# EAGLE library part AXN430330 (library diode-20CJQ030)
Matsushita P8 NARROW-PITCH CONNECTORS FOR PC BOARDS 30Pin Header NARROW-PITCH (0.8mm) CONNECTORS P8 SERIES FEATURES The product lineup consists of the low profile of: - 3 mm - 3.5 mm - 4 mm - 4.5 mm - 5 mm - 5.5 mm - 6 mm - 7 mm - 8 mm - 11.5 mm - 13 mm - 14 mm APPLICATIONS Small portable equipment, laptop computers, video equipment, radio communication, cellular telephones, etc. Please send any comments to: messi@users.sourceforge.net
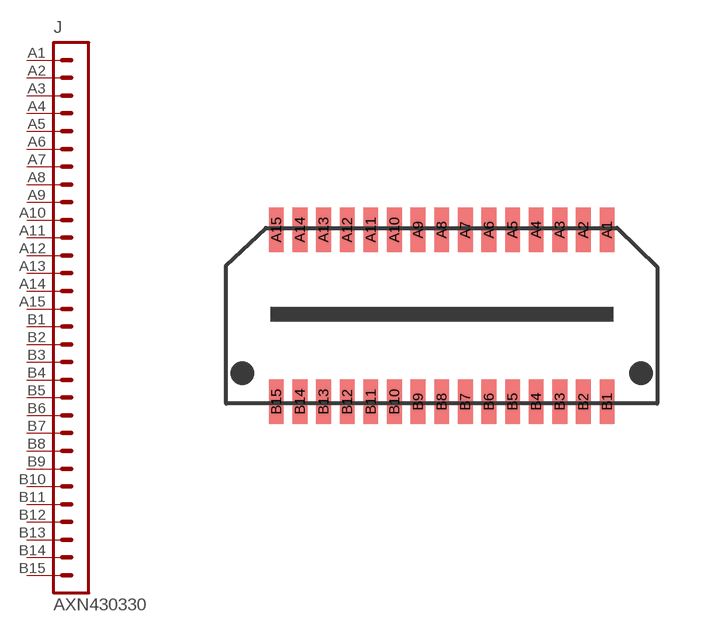
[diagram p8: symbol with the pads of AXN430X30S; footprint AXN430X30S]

Designator prefix J

## AXN430330  [AXN430X30S]
A1  1  pas
A2  2  pas
A3  3  pas
A4  4  pas
A5  5  pas
A6  6  pas
A7  7  pas
A8  8  pas
A9  9  pas
A10  10  pas
A11  11  pas
A12  12  pas
A13  13  pas
A14  14  pas
A15  15  pas
B1  16  pas
B2  17  pas
B3  18  pas
B4  19  pas
B5  20  pas
B6  21  pas
B7  22  pas
B8  23  pas
B9  24  pas
B10  25  pas
B11  26  pas
B12  27  pas
B13  28  pas
B14  29  pas
B15  30  pas

## Footprint AXN430X30S (pad centres in mm)
Matsushita NARROW-PITCH CONNECTORS FOR PC BOARDS 30Pin Header NARROW-PITCH (0.8mm) CONNECTORS P8 SERIES FEATURES The product lineup consists of the low profile of: - 3 mm - 3.5 mm - 4 mm - 4.5 mm - 5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
smd 0.5 x 1.5: A1 5.59,2.91; A2 4.79,2.91; A3 3.99,2.91; A4 3.19,2.91; A5 2.39,2.91; A6 1.59,2.91; A7 0.79,2.91; A8 -0.01,2.91; A9 -0.81,2.91; A10 -1.61,2.91; A11 -2.41,2.91; A12 -3.21,2.91; A13 -4.01,2.91; A14 -4.81,2.91; A15 -5.61,2.91; B1 5.59,-2.91; B2 4.79,-2.91; B3 3.99,-2.91; B4 3.19,-2.91; B5 2.39,-2.91; B6 1.59,-2.91; B7 0.79,-2.91; B8 -0.01,-2.91; B9 -0.81,-2.91; B10 -1.61,-2.91; B11 -2.41,-2.91; B12 -3.21,-2.91; B13 -4.01,-2.91; B14 -4.81,-2.91; B15 -5.61,-2.91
